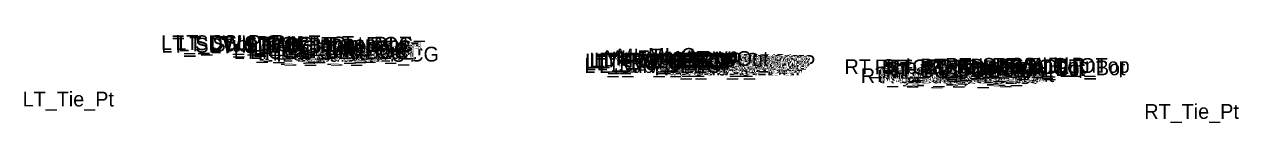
# Model space of a CAD drawing. Extents: x -26 to 4229, y -10 to 9523.
# Drawn here: x 1064.8 to 1228.9, y 5505.7 to 5517.6 of the extents above; entities that cross this region are included whole.
import ezdxf

# ---------------------------------------------------------------- set-up
doc = ezdxf.new("R2010")
doc.units = 0
doc.layers.add('Default', color=7, linetype='Continuous')

msp = doc.modelspace()

# ---------------------------------------------------------------- texts
at = {"layer": 'Default'}
for s, p in [('LT_SDWK_Out_Top', (1083.24, 5515.52)), ('LT_SDWK_Out_Bot', (1083.27, 5515.19)), ('LT_CSLP_Pnt', (1085.17, 5515.55)), ('LT_Sub_Trench_Out_DLT', (1085.58, 5515.35)), ('LT_SDWK_In_Top', (1089.86, 5515.42)), ('LT_SDWK_In_Bot', (1089.89, 5515.09)), ('LT_CG_Top_Face', (1094.76, 5515.31)), ('LT_CG_Top_BOC', (1095.28, 5515.31)), ('LT_CG1_Shelf_Out', (1093.05, 5514.34)), ('LT_CG_Bot_BOC', (1095.31, 5514.32)), ('LT_CG_Top_Gut', (1095.74, 5514.81)), ('LT_Sub_OEOP', (1096.37, 5514.1)), ('LT_Sub_OEOT_CG', (1096.87, 5513.98)), ('LT_CG_Bot_IE', (1099.41, 5514.23)), ('LT_Sub_OEOT', (1099.58, 5513.94)), ('LT_PV2_OEOT', (1099.67, 5514.57)), ('LT_PV3_OEOT', (1099.67, 5514.32)), ('LT_PV1_OEOT', (1100.24, 5514.82)), ('MI_Face In', (1143.15, 5513.48)), ('MI_Top In', (1144.86, 5513.73)), ('MI_Crown', (1149.07, 5513.81)), ('MI_Top Out', (1151.22, 5513.39)), ('LT_Sub_OEEOP', (1140.46, 5512.44)), ('LT_PV2_OEEOP', (1140.56, 5513.06)), ('LT_PV3_OEEOP', (1140.56, 5512.81)), ('LT_PV1_OEEOP', (1141.12, 5513.19)), ('LT_PV2_IEEOP', (1141.2, 5513.06)), ('LT_PV1_IEEOP', (1141.77, 5513.19)), ('LT_PV2_PGL1', (1142.13, 5513.06)), ('LT_PV3_PGL1', (1142.13, 5512.81)), ('LT_PV2_PGL', (1142.46, 5513.06)), ('LT_PV4_PGL', (1142.46, 5512.44)), ('LT_PV1_PGL', (1143.03, 5513.31)), ('MI_Bot In', (1144.13, 5513.31)), ('RT_Sub_OEEOP', (1149.92, 5512.1)), ('RT_PV2_OEEOP', (1150.01, 5512.72)), ('RT_PV3_OEEOP', (1150.01, 5512.47)), ('RT_PV1_OEEOP', (1150.58, 5512.85)), ('RT_PV2_IEEOP', (1150.66, 5512.72)), ('MI_Face Out', (1151.01, 5513.14)), ('RT_PV1_IEEOP', (1151.22, 5512.85)), ('RT_PV2_PGL1', (1151.58, 5512.72)), ('RT_PV3_PGL1', (1151.58, 5512.47)), ('RT_PV2_PGL', (1151.92, 5512.72)), ('RT_PV4_PGL', (1151.92, 5512.1)), ('MI_Bot Out', (1152.01, 5512.97)), ('RT_PV1_PGL', (1152.48, 5512.97)), ('RT_Sub_Trench_Out_DLT', (1175.62, 5512.29)), ('RT_CG_Top_Face', (1179.71, 5512.25)), ('RT_CG_Top_Gut', (1180.69, 5511.75)), ('RT_PV1_OEOT', (1181.19, 5511.9)), ('RT_CG_Top_BOC', (1181.24, 5512.25)), ('RT_SDWK_In_Top', (1185.81, 5512.36)), ('RT_SDWK_In_Bot', (1185.84, 5512.03)), ('RT_SDWK_Out_Top', (1189.19, 5512.46)), ('RT_SDWK_Out_Bot', (1189.22, 5512.13)), ('RT_Shld_O', (1195.54, 5512.45)), ('CSLP_Pnt', (1197.87, 5512.49)), ('RT_Sub_OEOT_CG', (1177.82, 5511.07)), ('RT_CG1_Shelf_Out', (1180, 5511.21)), ('RT_CG_Bot_IE', (1180.37, 5511.32)), ('RT_Sub_OEOT', (1180.53, 5511.03)), ('RT_PV2_OEOT', (1180.63, 5511.65)), ('RT_PV3_OEOT', (1180.63, 5511.4)), ('RT_CG_Bot_BOC', (1181.27, 5511.23)), ('RT_Sub_OEOP', (1183.82, 5510.95)), ('LT_Tie_Pt', (1064.53, 5507.91)), ('RT_Tie_Pt', (1216.14, 5506.24))]:
    msp.add_text(s, height=2, dxfattribs=at).set_placement(p)

doc.saveas('drawing.dxf')
